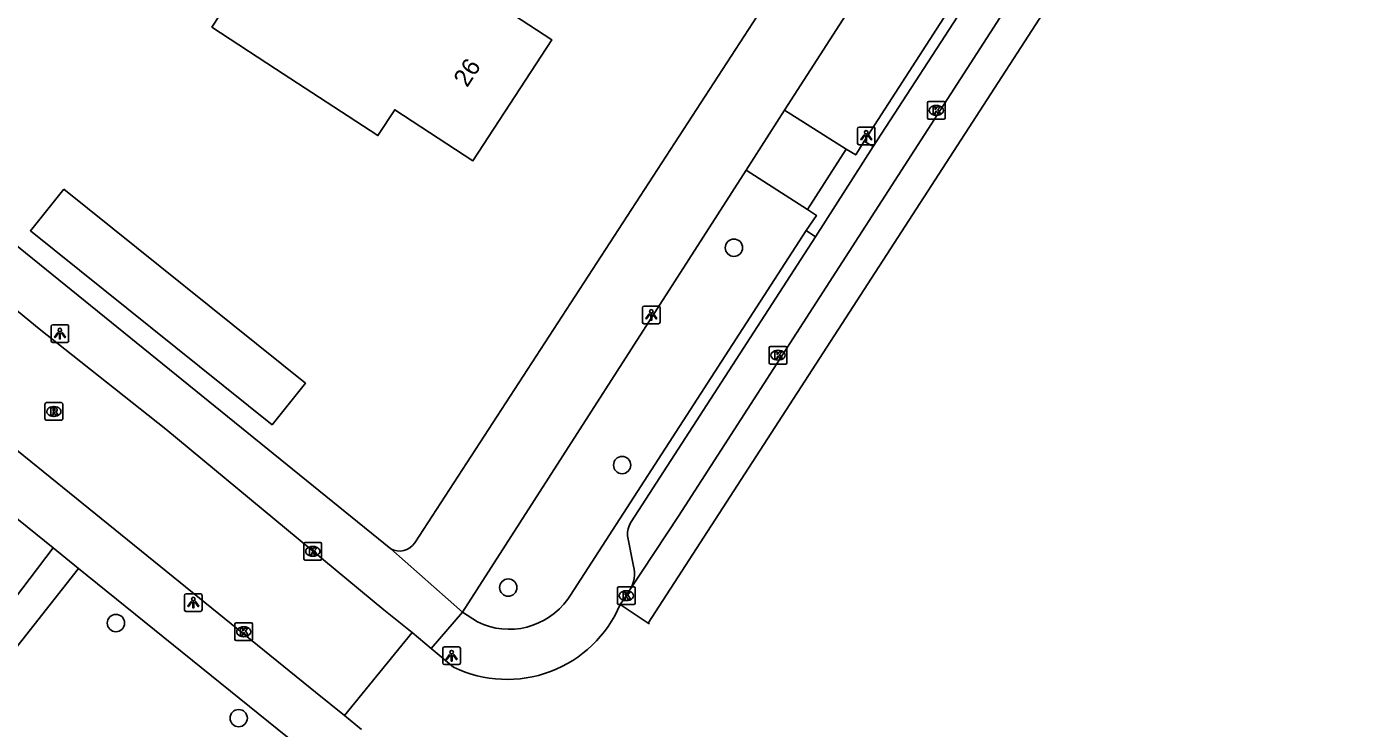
# Model space of a CAD drawing. Extents: x 161141 to 161601, y 381708 to 382245.
# Drawn here: x 161408.7 to 161484.6, y 381886.9 to 381926.5 of the extents above; entities that cross this region are included whole.
import ezdxf

# ---------------------------------------------------------------- set-up
doc = ezdxf.new("R2010")
doc.units = 0
for name, color, linetype in [('IMGEO_Boom', 7, 'Continuous'), ('IMGEO_Kolk', 7, 'Continuous'), ('IMGEO_Lichtpunt', 7, 'Continuous'), ('IMGEO_Pand', 7, 'Continuous'), ('IMGEO_Pand_nummerreeks', 7, 'Continuous'), ('IMGEO_Rijbaan_lokaal_gesloten', 7, 'Continuous'), ('IMGEO_Rijbaan_lokaal_open', 7, 'Continuous'), ('IMGEO_Rioolput', 7, 'Continuous'), ('IMGEO_Voetpad_open', 7, 'Continuous')]:
    doc.layers.add(name, color=color, linetype=linetype)

msp = doc.modelspace()

# ---------------------------------------------------------------- linework, layer by layer
at = {"layer": 'IMGEO_Boom'}
for centre in [(161448.728, 381914.031), (161442.404, 381901.737), (161435.96, 381894.811), (161413.761, 381892.803), (161420.709, 381887.423)]:
    msp.add_circle(centre, 0.489, dxfattribs=at)
at = {"layer": 'IMGEO_Kolk'}
for p, q in [((161459.751, 381922.3), (161460.603, 381922.3)), ((161459.676, 381921.374), (161459.676, 381922.226)), ((161460.187, 381921.52), (161460.162, 381921.52)), ((161460.164, 381922.08), (161460.189, 381922.08)), ((161460.677, 381922.226), (161460.677, 381921.374)), ((161460.603, 381921.3), (161459.751, 381921.3)), ((161450.725, 381907.526), (161450.725, 381908.378)), ((161450.8, 381908.452), (161451.652, 381908.452)), ((161451.213, 381908.232), (161451.238, 381908.232)), ((161451.726, 381908.378), (161451.726, 381907.526)), ((161451.652, 381907.452), (161450.8, 381907.452)), ((161451.236, 381907.672), (161451.211, 381907.672)), ((161424.402, 381896.433), (161424.402, 381897.285)), ((161424.477, 381897.359), (161425.329, 381897.359)), ((161425.403, 381897.285), (161425.403, 381896.433)), ((161424.913, 381896.579), (161424.888, 381896.579)), ((161424.89, 381897.139), (161424.915, 381897.139)), ((161425.329, 381896.359), (161424.477, 381896.359)), ((161442.14, 381893.923), (161442.14, 381894.775)), ((161442.215, 381894.849), (161443.067, 381894.849)), ((161442.628, 381894.629), (161442.653, 381894.629)), ((161443.141, 381894.775), (161443.141, 381893.923)), ((161443.067, 381893.849), (161442.215, 381893.849)), ((161442.651, 381894.069), (161442.626, 381894.069)), ((161420.495, 381891.884), (161420.495, 381892.736)), ((161420.57, 381892.81), (161421.422, 381892.81)), ((161421.496, 381892.736), (161421.496, 381891.884)), ((161421.006, 381892.03), (161420.981, 381892.03)), ((161420.983, 381892.59), (161421.008, 381892.59)), ((161421.422, 381891.81), (161420.57, 381891.81))]:
    msp.add_line(p, q, dxfattribs=at)
for points in [[(161459.751, 381922.3), (161460.603, 381922.3)], [(161459.676, 381921.374), (161459.676, 381922.226)], [(161459.997, 381922), (161460.12, 381922), (161460.12, 381921.849), (161460.25, 381922), (161460.414, 381922), (161460.268, 381921.849), (161460.421, 381921.6), (161460.269, 381921.6), (161460.184, 381921.764), (161460.12, 381921.697), (161460.12, 381921.6), (161459.997, 381921.6), (161459.997, 381922)], [(161460.677, 381922.226), (161460.677, 381921.374)], [(161460.603, 381921.3), (161459.751, 381921.3)], [(161450.725, 381907.526), (161450.725, 381908.378)], [(161450.8, 381908.452), (161451.652, 381908.452)], [(161451.046, 381908.152), (161451.169, 381908.152), (161451.169, 381908.001), (161451.299, 381908.152), (161451.463, 381908.152), (161451.317, 381908.001), (161451.47, 381907.752), (161451.318, 381907.752), (161451.233, 381907.916), (161451.169, 381907.849), (161451.169, 381907.752), (161451.046, 381907.752), (161451.046, 381908.152)], [(161451.726, 381908.378), (161451.726, 381907.526)], [(161451.652, 381907.452), (161450.8, 381907.452)], [(161424.402, 381896.433), (161424.402, 381897.285)], [(161424.477, 381897.359), (161425.329, 381897.359)], [(161425.403, 381897.285), (161425.403, 381896.433)], [(161424.723, 381897.059), (161424.846, 381897.059), (161424.846, 381896.908), (161424.976, 381897.059), (161425.14, 381897.059), (161424.994, 381896.908), (161425.147, 381896.659), (161424.995, 381896.659), (161424.91, 381896.823), (161424.846, 381896.756), (161424.846, 381896.659), (161424.723, 381896.659), (161424.723, 381897.059)], [(161425.329, 381896.359), (161424.477, 381896.359)], [(161442.14, 381893.923), (161442.14, 381894.775)], [(161442.215, 381894.849), (161443.067, 381894.849)], [(161442.461, 381894.549), (161442.584, 381894.549), (161442.584, 381894.398), (161442.714, 381894.549), (161442.878, 381894.549), (161442.732, 381894.398), (161442.885, 381894.149), (161442.733, 381894.149), (161442.648, 381894.313), (161442.584, 381894.246), (161442.584, 381894.149), (161442.461, 381894.149), (161442.461, 381894.549)], [(161443.141, 381894.775), (161443.141, 381893.923)], [(161443.067, 381893.849), (161442.215, 381893.849)], [(161420.495, 381891.884), (161420.495, 381892.736)], [(161420.57, 381892.81), (161421.422, 381892.81)], [(161421.496, 381892.736), (161421.496, 381891.884)], [(161420.816, 381892.51), (161420.939, 381892.51), (161420.939, 381892.359), (161421.069, 381892.51), (161421.233, 381892.51), (161421.087, 381892.359), (161421.24, 381892.11), (161421.088, 381892.11), (161421.003, 381892.274), (161420.939, 381892.207), (161420.939, 381892.11), (161420.816, 381892.11), (161420.816, 381892.51)], [(161421.422, 381891.81), (161420.57, 381891.81)]]:
    msp.add_lwpolyline(points, dxfattribs=at)
for centre, start, end in [((161459.753, 381922.224), 91.55205, 178.44795), ((161459.753, 381922.224), 91.55205, 178.44795), ((161460.601, 381922.224), 1.55205, 88.44795), ((161460.601, 381922.224), 1.55205, 88.44795), ((161459.753, 381921.376), 181.55205, 268.44795), ((161459.753, 381921.376), 181.55205, 268.44795), ((161460.601, 381921.376), 271.55205, 358.44795), ((161460.601, 381921.376), 271.55205, 358.44795), ((161450.802, 381908.376), 91.55205, 178.44795), ((161450.802, 381908.376), 91.55205, 178.44795), ((161451.65, 381908.376), 1.55205, 88.44795), ((161451.65, 381908.376), 1.55205, 88.44795), ((161450.802, 381907.528), 181.55205, 268.44795), ((161450.802, 381907.528), 181.55205, 268.44795), ((161451.65, 381907.528), 271.55205, 358.44795), ((161451.65, 381907.528), 271.55205, 358.44795), ((161424.479, 381897.283), 91.55205, 178.44795), ((161424.479, 381897.283), 91.55205, 178.44795), ((161425.327, 381897.283), 1.55205, 88.44795), ((161425.327, 381897.283), 1.55205, 88.44795), ((161424.479, 381896.435), 181.55205, 268.44795), ((161424.479, 381896.435), 181.55205, 268.44795), ((161425.327, 381896.435), 271.55205, 358.44795), ((161425.327, 381896.435), 271.55205, 358.44795), ((161442.217, 381894.773), 91.55205, 178.44795), ((161442.217, 381894.773), 91.55205, 178.44795), ((161443.065, 381894.773), 1.55205, 88.44795), ((161443.065, 381894.773), 1.55205, 88.44795), ((161442.217, 381893.925), 181.55205, 268.44795), ((161442.217, 381893.925), 181.55205, 268.44795), ((161443.065, 381893.925), 271.55205, 358.44795), ((161443.065, 381893.925), 271.55205, 358.44795), ((161420.572, 381892.734), 91.55205, 178.44795), ((161420.572, 381892.734), 91.55205, 178.44795), ((161421.42, 381892.734), 1.55205, 88.44795), ((161421.42, 381892.734), 1.55205, 88.44795), ((161420.572, 381891.886), 181.55205, 268.44795), ((161420.572, 381891.886), 181.55205, 268.44795), ((161421.42, 381891.886), 271.55205, 358.44795), ((161421.42, 381891.886), 271.55205, 358.44795)]:
    msp.add_arc(centre, 0.0765, start, end, dxfattribs=at)
for centre, major_axis, ratio, start_param, end_param in [((161460.163, 381921.8), (-0.387, 0.002), 0.722429, 4.712389, 7.853982), ((161460.188, 381921.8), (-0.39, 0.002), 0.717154, 1.570796, 4.712389), ((161451.212, 381907.952), (-0.387, 0.002), 0.722429, 4.712389, 7.853982), ((161451.237, 381907.952), (-0.39, 0.002), 0.717154, 1.570796, 4.712389), ((161424.889, 381896.859), (-0.387, 0.002), 0.722429, 4.712389, 7.853982), ((161424.914, 381896.859), (-0.39, 0.002), 0.717154, 1.570796, 4.712389), ((161442.627, 381894.349), (-0.387, 0.002), 0.722429, 4.712389, 7.853982), ((161442.652, 381894.349), (-0.39, 0.002), 0.717154, 1.570796, 4.712389), ((161420.982, 381892.31), (-0.387, 0.002), 0.722429, 4.712389, 7.853982), ((161421.007, 381892.31), (-0.39, 0.002), 0.717154, 1.570796, 4.712389)]:
    msp.add_ellipse(centre, major_axis=major_axis, ratio=ratio, start_param=start_param, end_param=end_param, dxfattribs=at)
at = {"layer": 'IMGEO_Lichtpunt'}
for p, q in [((161455.715, 381920.762), (161455.715, 381919.955)), ((161455.715, 381920.762), (161455.715, 381919.955)), ((161456.617, 381920.857), (161455.809, 381920.857)), ((161456.617, 381920.857), (161455.809, 381920.857)), ((161456.711, 381919.955), (161456.711, 381920.762)), ((161456.711, 381919.955), (161456.711, 381920.762)), ((161455.809, 381919.861), (161456.617, 381919.861)), ((161455.809, 381919.861), (161456.617, 381919.861)), ((161443.556, 381910.635), (161443.556, 381909.828)), ((161443.556, 381910.635), (161443.556, 381909.828)), ((161444.458, 381910.73), (161443.65, 381910.73)), ((161444.458, 381910.73), (161443.65, 381910.73)), ((161444.552, 381909.828), (161444.552, 381910.635)), ((161444.552, 381909.828), (161444.552, 381910.635)), ((161410.093, 381909.577), (161410.093, 381908.77)), ((161410.093, 381909.577), (161410.093, 381908.77)), ((161410.995, 381909.672), (161410.187, 381909.672)), ((161410.995, 381909.672), (161410.187, 381909.672)), ((161411.089, 381908.77), (161411.089, 381909.577)), ((161411.089, 381908.77), (161411.089, 381909.577)), ((161443.65, 381909.734), (161444.458, 381909.734)), ((161443.65, 381909.734), (161444.458, 381909.734)), ((161410.187, 381908.676), (161410.995, 381908.676)), ((161410.187, 381908.676), (161410.995, 381908.676)), ((161417.642, 381894.364), (161417.642, 381893.557)), ((161417.642, 381894.364), (161417.642, 381893.557)), ((161418.544, 381894.459), (161417.736, 381894.459)), ((161418.544, 381894.459), (161417.736, 381894.459)), ((161418.638, 381893.557), (161418.638, 381894.364)), ((161418.638, 381893.557), (161418.638, 381894.364)), ((161417.736, 381893.463), (161418.544, 381893.463)), ((161417.736, 381893.463), (161418.544, 381893.463)), ((161432.256, 381891.359), (161432.256, 381890.552)), ((161432.256, 381891.359), (161432.256, 381890.552)), ((161433.158, 381891.454), (161432.35, 381891.454)), ((161433.158, 381891.454), (161432.35, 381891.454)), ((161433.252, 381890.552), (161433.252, 381891.359)), ((161433.252, 381890.552), (161433.252, 381891.359)), ((161432.35, 381890.458), (161433.158, 381890.458)), ((161432.35, 381890.458), (161433.158, 381890.458))]:
    msp.add_line(p, q, dxfattribs=at)
for points in [[(161456.089, 381920.426), (161456.128, 381920.398), (161455.94, 381920.136), (161455.902, 381920.163), (161456.089, 381920.426)], [(161456.191, 381920.378), (161456.238, 381920.378), (161456.238, 381920.056), (161456.191, 381920.056), (161456.191, 381920.378)], [(161456.301, 381920.398), (161456.339, 381920.425), (161456.526, 381920.163), (161456.487, 381920.135), (161456.301, 381920.398)], [(161443.93, 381910.299), (161443.969, 381910.271), (161443.781, 381910.009), (161443.743, 381910.036), (161443.93, 381910.299)], [(161444.032, 381910.251), (161444.079, 381910.251), (161444.079, 381909.929), (161444.032, 381909.929), (161444.032, 381910.251)], [(161444.142, 381910.271), (161444.18, 381910.298), (161444.367, 381910.036), (161444.328, 381910.008), (161444.142, 381910.271)], [(161410.467, 381909.241), (161410.506, 381909.213), (161410.318, 381908.951), (161410.28, 381908.978), (161410.467, 381909.241)], [(161410.569, 381909.193), (161410.616, 381909.193), (161410.616, 381908.871), (161410.569, 381908.871), (161410.569, 381909.193)], [(161410.679, 381909.213), (161410.717, 381909.24), (161410.904, 381908.978), (161410.865, 381908.95), (161410.679, 381909.213)], [(161418.016, 381894.028), (161418.055, 381894), (161417.867, 381893.738), (161417.829, 381893.765), (161418.016, 381894.028)], [(161418.118, 381893.98), (161418.165, 381893.98), (161418.165, 381893.658), (161418.118, 381893.658), (161418.118, 381893.98)], [(161418.228, 381894), (161418.266, 381894.027), (161418.453, 381893.765), (161418.414, 381893.737), (161418.228, 381894)], [(161432.63, 381891.023), (161432.669, 381890.995), (161432.481, 381890.733), (161432.443, 381890.76), (161432.63, 381891.023)], [(161432.732, 381890.975), (161432.779, 381890.975), (161432.779, 381890.653), (161432.732, 381890.653), (161432.732, 381890.975)], [(161432.842, 381890.995), (161432.88, 381891.022), (161433.067, 381890.76), (161433.028, 381890.732), (161432.842, 381890.995)]]:
    msp.add_lwpolyline(points, dxfattribs=at)
for centre in [(161456.214, 381920.56), (161444.055, 381910.433), (161410.592, 381909.375), (161418.141, 381894.162), (161432.755, 381891.157)]:
    msp.add_circle(centre, 0.0994, dxfattribs=at)
for centre, start, end in [((161455.809, 381920.762), 90, 180), ((161455.809, 381920.762), 90, 180), ((161456.617, 381920.762), 0, 90), ((161456.617, 381920.762), 0, 90), ((161455.809, 381919.955), 180, 270), ((161455.809, 381919.955), 180, 270), ((161456.617, 381919.955), 270, 0), ((161456.617, 381919.955), 270, 360), ((161443.65, 381910.635), 90, 180), ((161443.65, 381910.635), 90, 180), ((161444.458, 381910.635), 0, 90), ((161444.458, 381910.635), 0, 90), ((161410.187, 381909.577), 90, 180), ((161410.187, 381909.577), 90, 180), ((161410.995, 381909.577), 0, 90), ((161410.995, 381909.577), 0, 90), ((161443.65, 381909.828), 180, 270), ((161443.65, 381909.828), 180, 270), ((161444.458, 381909.828), 270, 0), ((161444.458, 381909.828), 270, 360), ((161410.187, 381908.77), 180, 270), ((161410.187, 381908.77), 180, 270), ((161410.995, 381908.77), 270, 0), ((161410.995, 381908.77), 270, 360), ((161417.736, 381894.364), 90, 180), ((161417.736, 381894.364), 90, 180), ((161418.544, 381894.364), 0, 90), ((161418.544, 381894.364), 0, 90), ((161417.736, 381893.557), 180, 270), ((161417.736, 381893.557), 180, 270), ((161418.544, 381893.557), 270, 0), ((161418.544, 381893.557), 270, 360), ((161432.35, 381891.359), 90, 180), ((161432.35, 381891.359), 90, 180), ((161433.158, 381891.359), 0, 90), ((161433.158, 381891.359), 0, 90), ((161432.35, 381890.552), 180, 270), ((161432.35, 381890.552), 180, 270), ((161433.158, 381890.552), 270, 0), ((161433.158, 381890.552), 270, 360)]:
    msp.add_arc(centre, 0.0946, start, end, dxfattribs=at)
at = {"layer": 'IMGEO_Pand'}
for points in [[(161419.303, 381942.671), (161421.878, 381940.989), (161432.947, 381933.757), (161430.94, 381930.685), (161438.43, 381925.79), (161433.961, 381918.951), (161429.542, 381921.839), (161428.584, 381920.374), (161422.791, 381924.16), (161419.192, 381926.512), (161420.883, 381929.103), (161416.127, 381932.149), (161417.632, 381934.492), (161415.057, 381936.174), (161419.303, 381942.671)], [(161410.809, 381917.337), (161424.483, 381906.363), (161422.601, 381904.018), (161408.927, 381914.992), (161410.809, 381917.337)]]:
    msp.add_lwpolyline(points, dxfattribs=at)
at = {"layer": 'IMGEO_Rijbaan_lokaal_gesloten'}
for points in [[(161482.323, 381955.826), (161445.595, 381898.855), (161442.845, 381894.672)], [(161484.559, 381955.638), (161443.88, 381892.8)], [(161442.845, 381894.672), (161442.78, 381894.574), (161442.641, 381894.349), (161442.292, 381893.851)]]:
    msp.add_lwpolyline(points, dxfattribs=at)
at = {"layer": 'IMGEO_Rijbaan_lokaal_open'}
for points in [[(161430.53, 381892.26), (161428.93, 381893.541), (161416.582, 381903.762), (161409.42, 381909.443), (161405.146, 381912.95), (161401.483, 381915.955), (161397.742, 381918.904), (161394.58, 381921.397), (161388.533, 381926.301), (161384.971, 381929.006), (161381.728, 381931.469), (161381.315, 381931.756), (161376.383, 381935.18), (161370.251, 381939.135), (161367.432, 381940.939), (161364.318, 381942.933), (161361.946, 381944.451), (161354.44, 381949.434), (161345.5, 381955.194), (161345.132, 381955.433), (161341.968, 381957.49), (161334.965, 381962.043), (161325.373, 381968.263), (161318.237, 381972.89)], [(161426.69, 381887.564), (161425.057, 381888.885), (161404.152, 381905.797), (161399.947, 381909.192), (161394.957, 381913.221), (161391.403, 381916.091), (161386.448, 381920.091)], [(161410.212, 381897.05), (161396.293, 381878.738), (161395.877, 381878.224), (161395.275, 381877.818), (161393.345, 381877.126), (161385.244, 381874.499), (161385.019, 381874.335), (161383.219, 381872.094), (161381.677, 381873.144)], [(161410.212, 381897.05), (161411.648, 381895.891)], [(161396.286, 381876.416), (161411.648, 381895.891)], [(161443.88, 381892.8), (161442.292, 381893.851)], [(161443.88, 381892.8), (161443.951, 381892.753)], [(161430.53, 381892.26), (161426.69, 381887.564)], [(161431.607, 381891.362), (161430.53, 381892.26)], [(161432.872, 381890.307), (161431.607, 381891.362)], [(161426.69, 381887.564), (161427.654, 381886.777)]]:
    msp.add_lwpolyline(points, dxfattribs=at)
msp.add_arc((161435.898, 381896.555), 6.942, 244.15497, 337.07972, dxfattribs=at)
at = {"layer": 'IMGEO_Rioolput'}
for p, q in [((161409.75, 381904.344), (161409.75, 381905.196)), ((161409.825, 381905.27), (161410.677, 381905.27)), ((161410.238, 381905.05), (161410.263, 381905.05)), ((161410.751, 381905.196), (161410.751, 381904.344)), ((161410.677, 381904.27), (161409.825, 381904.27)), ((161410.261, 381904.49), (161410.236, 381904.49))]:
    msp.add_line(p, q, dxfattribs=at)
for points in [[(161409.75, 381904.344), (161409.75, 381905.196)], [(161409.825, 381905.27), (161410.677, 381905.27)], [(161410.339, 381904.968), (161410.087, 381904.97), (161410.087, 381904.57)], [(161410.265, 381904.889), (161410.211, 381904.889), (161410.211, 381904.808)], [(161410.751, 381905.196), (161410.751, 381904.344)], [(161410.677, 381904.27), (161409.825, 381904.27)], [(161410.087, 381904.57), (161410.211, 381904.57), (161410.211, 381904.732), (161410.222, 381904.732)], [(161410.211, 381904.808), (161410.263, 381904.808)], [(161410.269, 381904.703), (161410.34, 381904.57), (161410.48, 381904.57), (161410.415, 381904.696)]]:
    msp.add_lwpolyline(points, dxfattribs=at)
for centre, radius, start, end in [((161409.827, 381905.194), 0.0765, 91.55205, 178.44795), ((161409.827, 381905.194), 0.0765, 91.55205, 178.44795), ((161410.271, 381904.793), 0.0964, 77.00612, 93.18647), ((161410.285, 381904.85), 0.0378, 276.66336, 79.67722), ((161410.338, 381904.858), 0.109, 350.36119, 89.41601), ((161410.336, 381904.858), 0.112, 277.58423, 350.98172), ((161410.675, 381905.194), 0.0765, 1.55205, 88.44795), ((161410.675, 381905.194), 0.0765, 1.55205, 88.44795), ((161409.827, 381904.346), 0.0765, 181.55205, 268.44795), ((161409.827, 381904.346), 0.0765, 181.55205, 268.44795), ((161410.221, 381904.679), 0.0533, 26.02933, 88.69889), ((161410.247, 381904.997), 0.19, 274.7715, 282.96867), ((161410.32, 381904.643), 0.108, 29.51342, 73.79051), ((161410.675, 381904.346), 0.0765, 271.55205, 358.44795), ((161410.675, 381904.346), 0.0765, 271.55205, 358.44795)]:
    msp.add_arc(centre, radius, start, end, dxfattribs=at)
for centre, major_axis, ratio, start_param, end_param in [((161410.237, 381904.77), (-0.387, 0.002), 0.722429, 4.712389, 7.853982), ((161410.262, 381904.77), (-0.39, 0.002), 0.717154, 1.570796, 4.712389)]:
    msp.add_ellipse(centre, major_axis=major_axis, ratio=ratio, start_param=start_param, end_param=end_param, dxfattribs=at)
at = {"layer": 'IMGEO_Voetpad_open'}
for points in [[(161278.294, 382002.287), (161281.877, 382000), (161299.823, 381988.353), (161310.674, 381981.109), (161322.611, 381973.432), (161322.712, 381973.551), (161378.924, 381936.994), (161385.641, 381932.206), (161392.817, 381926.552), (161429.313, 381896.994)], [(161430.666, 381897.334), (161474.804, 381965.241)], [(161451.6, 381921.815), (161458.183, 381932.073)], [(161461.576, 381928.548), (161456.096, 381920.062)], [(161462.089, 381928.215), (161456.613, 381919.75)], [(161451.6, 381921.815), (161449.423, 381918.424)], [(161455.089, 381919.607), (161451.6, 381921.815)], [(161456.096, 381920.062), (161455.625, 381919.283), (161455.089, 381919.607)], [(161456.613, 381919.75), (161456.096, 381920.062)], [(161452.891, 381916.189), (161455.089, 381919.607)], [(161456.613, 381919.75), (161453.345, 381914.652)], [(161433.377, 381893.414), (161449.423, 381918.424)], [(161449.423, 381918.424), (161452.891, 381916.189)], [(161384.753, 381917.612), (161384.887, 381917.504), (161410.212, 381897.05)], [(161452.819, 381915.007), (161453.392, 381915.857), (161452.891, 381916.189)], [(161452.819, 381915.007), (161439.478, 381894.385), (161439.331, 381894.161)], [(161453.345, 381914.652), (161452.819, 381915.007)], [(161453.345, 381914.652), (161442.912, 381898.524)], [(161442.701, 381897.727), (161443.056, 381896.028)], [(161429.313, 381896.994), (161433.377, 381893.414)], [(161411.648, 381895.891), (161423.964, 381885.944), (161425.633, 381884.432)], [(161433.377, 381893.414), (161431.607, 381891.362)], [(161434.212, 381892.863), (161433.377, 381893.414)]]:
    msp.add_lwpolyline(points, dxfattribs=at)
for centre, radius, start, end in [((161444.285, 381897.734), 1.584, 150.08338, 180.25971), ((161429.799, 381897.922), 1.048, 242.36645, 325.84549), ((161441.317, 381895.604), 1.79, 328.61329, 13.69758), ((161436.005, 381896.536), 4.087, 243.97976, 324.47691)]:
    msp.add_arc(centre, radius, start, end, dxfattribs=at)

# ---------------------------------------------------------------- texts
at = {"layer": 'IMGEO_Pand_nummerreeks'}
msp.add_text('26', height=1, rotation=56.83741, dxfattribs=at).set_placement((161433.634, 381923.058))

doc.saveas('drawing.dxf')
